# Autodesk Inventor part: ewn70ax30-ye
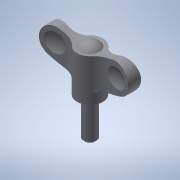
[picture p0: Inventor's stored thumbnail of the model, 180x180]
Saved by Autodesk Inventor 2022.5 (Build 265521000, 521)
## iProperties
Created: 2016-12
Part Number: ewn70ax30-ye
Material: 一般
Document SubType Name: Modeling
Designer: imaocorp
Density: 1 g/cm^3
Appearance: 既定
Author: imaocorp
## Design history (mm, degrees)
node "ewn70ax30-ye.x_t1"
node "ewn70ax30-ye"
node "Base1"
